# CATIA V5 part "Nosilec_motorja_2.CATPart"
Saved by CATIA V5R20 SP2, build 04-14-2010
Part number: Nos_M_1
Bounding box of the stored display mesh (mm): x -36.243 to 9.957, y -4.737 to 33.233, z 0 to 6
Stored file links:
  C:\Documents and Settings\Administrator\My Documents\Hobi_dokumenti\CAD_CNC\Clap_CATIA\Nosilec_motorja_2.CATPart
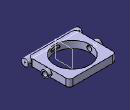
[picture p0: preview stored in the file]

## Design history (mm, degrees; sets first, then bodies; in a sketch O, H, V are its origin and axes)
Set1
  DatumSurface1
  Plane1: stored without definition
  Plane2: stored without definition
  DatumCurve1
  Plane3 to Plane7: stored without definition
  Point1: type Center, Curve edge [face of Pad1 from Sketch1.L4 | face of Pocket1 from Sketch2.A1]
  Point2: type Center, Curve edge [face of Pad1 from Sketch1.L2 | face of Pocket1 from Sketch2.A1]
  Plane8: type Offset, RefPlane face of Pad1 from Sketch1.L4, Offset -20, reversed
  Point3: stored without definition
  Point4: type Center, Curve edge [face of Pad3 | end face of Pad3]
  Point5: type Center, Curve edge [start face of Pad3 | face of Pad3]
  Line1: type PtPt, FirstPoint Point4, SecondPoint Point5
Body1 (main body)
  Sketch1 on face of DatumSurface1, origin (0, 0, 0), H (1, 0, 0), V (0, 1, 0)
    line L1 (-33.1429, 33.2326) -> (6.8571, 33.2326)
    line L2 (6.8571, 33.2326) -> (6.8571, -1.7674)
    line L3 (6.8571, -1.7674) -> (-33.1429, -1.7674)
    line L4 (-33.1429, -1.7674) -> (-33.1429, 33.2326)
    reference intersected line E2 through (0, 0) direction (0, 1) from yz-plane
    reference intersected line E3 through (0, 0) direction (-1, 0) from zx-plane
    reference intersected line E4 through (-13.1429, 0) direction (0, 1) from Plane1
    reference intersected line E5 through (0, 15.7326) direction (-1, 0) from Plane3
    distance L1 L3 = 35
    distance E4 L4 = 20
    length L3 = 40
    distance E5 L1 = 17.5
    horizontal: L1 H, L3 H, E3 H
    vertical: L2 V, L4 V, E2 V
    perpendicularity: E2 L1
  Pad1: profile Sketch1, direction (0, 0, 1), length 6
  Fillet1: radius 3, on edge [face of Pad1 from Sketch1.L3 | face of Pad1 from Sketch1.L4]; edge [face of Pad1 from Sketch1.L2 | face of Pad1 from Sketch1.L3]; edge [face of Pad1 from Sketch1.L4 | face of Pad1 from Sketch1.L1]; edge [face of Pad1 from Sketch1.L1 | face of Pad1 from Sketch1.L2]
  Sketch2 on Plane4, origin (-13.1429, 0, 0), H (0, 1, 0), V (0, 0, 1)
    circle A1 centre (15.2634, 3) radius 2
    point P1 (15.2634, 3)
    reference intersected line E1 through (0, -54) direction (-1, 0) from Plane7
    radius A1 = 2
    distance E1 P1 = 57
  Pocket1: profile Sketch2, direction (1, 0, 0), length 30, mirrored extent
  Sketch3 on face of Pad1 from Sketch1.L4, origin (-33.1429, 0, 0), H (0, -1, 0), V (0, 0, 1)
    circle A1 centre (-15.2634, 3) radius 2
    circle A2 centre (-15.2634, 3) radius 3
    radius A2 = 3
    radius A1 = 2
  Pad2: profile Sketch3, direction (-1, 0, 0), length 3.1
  Mirror1: of Pad2, Sketch3, about Plane8
  Sketch4 on end face of Pad1, origin (0, 0, 6), H (1, 0, 0), V (0, 1, 0)
    circle A1 centre (-13.1429, 15.7326) radius 15
    point P1 (-13.1429, 15.7326)
    reference projected point E1 (-13.1429, 15.7326) from Point3
    radius A1 = 15
    distance E1 P1 = 0
  Pocket2: profile Sketch4, direction (0, 0, -1), length 7
  Sketch5 on Plane8, origin (-13.1429, 0, 0), H (0, 1, 0), V (0, 0, 1)
    circle A1 centre (-1.7366, 3) radius 3
    point P1 (-1.7366, 3)
    reference projected point E1 (15.2634, 3) from Point2
    radius A1 = 3
    distance H P1 = 3
    distance E1 P1 = 17
  Pad3: profile Sketch5, direction (1, 0, 0), length 23.1, mirrored extent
